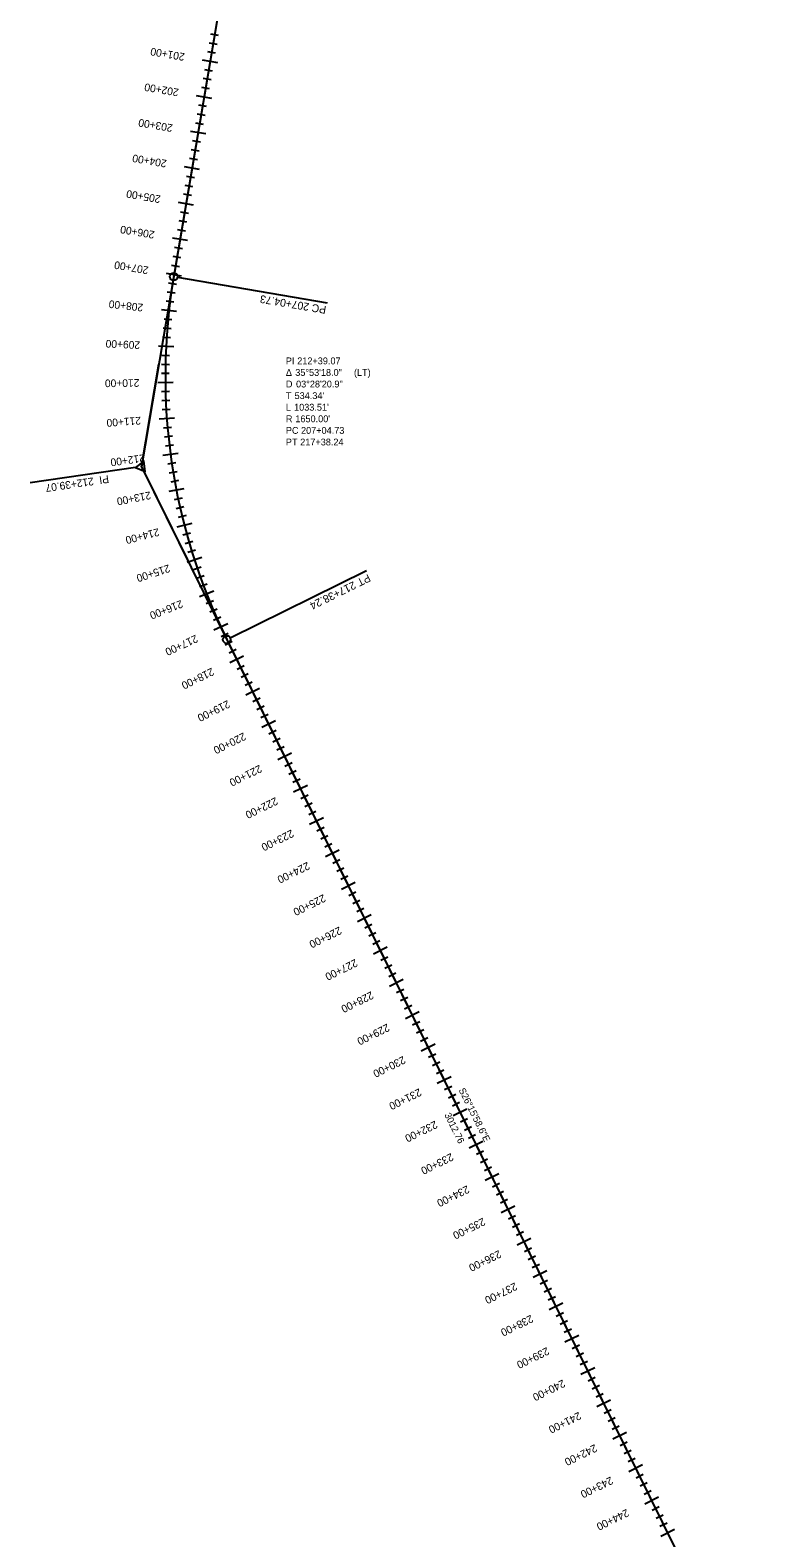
# Model space of a CAD drawing. Extents: x 2823077 to 2858057, y 1248786 to 1289821.
# Drawn here: x 2838680 to 2840753, y 1274641 to 1278821 of the extents above; entities that cross this region are included whole.
import ezdxf

# ---------------------------------------------------------------- set-up
doc = ezdxf.new("R2010")
doc.units = 0
for name, color, linetype in [('_CIVIL_CONSTRUCTION', 7, 'Continuous'), ('Default', 7, 'Continuous'), ('TL_Earth Shoulder Sub', 7, 'Continuous'), ('TL_End Condition Hinge', 7, 'Continuous'), ('TL_Pavement Centerline Sub', 7, 'Continuous'), ('TL_Pavement Edge', 7, 'Continuous'), ('TL_Pavement Edge Sub', 7, 'Continuous'), ('TL_Shoulder Edge', 7, 'Continuous'), ('TL_Shoulder Edge Sub', 7, 'Continuous')]:
    doc.layers.add(name, color=color, linetype=linetype)

msp = doc.modelspace()

# ---------------------------------------------------------------- linework, layer by layer
at = {"layer": '_CIVIL_CONSTRUCTION'}
for p, q in [((2839406.5, 1280075.4), (2839077.9, 1278137.4)), ((2839225.1, 1277131.4), (2840558.4, 1274429.8))]:
    msp.add_line(p, q, dxfattribs=at)
msp.add_arc((2840704.7, 1277861.6), 1650, 170.378, 206.2663, dxfattribs=at)
at = {"layer": 'Default'}
for p, q in [((2839540.6, 1280866.7), (2838988.6, 1277610.6)), ((2838988.6, 1277610.6), (2840753.1, 1274035.2))]:
    msp.add_line(p, q, dxfattribs=at)
msp.add_arc((2840704.7, 1277861.6), 1650, 170.378, 206.2663, dxfattribs=at)
at = {"layer": 'TL_Earth Shoulder Sub'}
for p, q in [((2839077.9, 1278137.4), (2839077.9, 1278137.4)), ((2839503.9, 1278065.2), (2839503.9, 1278065.2)), ((2838988.6, 1277610.6), (2838988.6, 1277610.6)), ((2838679.9, 1277565.4), (2838679.9, 1277565.4)), ((2839612.5, 1277322.6), (2839612.5, 1277322.6)), ((2839225.1, 1277131.4), (2839225.1, 1277131.4))]:
    msp.add_line(p, q, dxfattribs=at)
for centre in [(2839077.9, 1278137.4), (2839225.1, 1277131.4)]:
    msp.add_circle(centre, 10.7, dxfattribs=at)
at = {"layer": 'TL_Pavement Centerline Sub'}
for p, q in [((2839200.1, 1278730.1), (2839158.2, 1278737.2)), ((2839183.4, 1278631.5), (2839141.5, 1278638.6)), ((2839166.6, 1278532.9), (2839124.8, 1278540)), ((2839149.9, 1278434.3), (2839108.1, 1278441.4)), ((2839133.2, 1278335.7), (2839091.3, 1278342.8)), ((2839116.5, 1278237.1), (2839074.6, 1278244.2)), ((2839099.8, 1278138.5), (2839057.9, 1278145.6)), ((2839086, 1278040.7), (2839043.7, 1278045.4)), ((2839078.1, 1277942.4), (2839035.7, 1277944.5)), ((2839076.2, 1277843.7), (2839033.7, 1277843.2)), ((2839080.3, 1277745.1), (2839037.9, 1277742)), ((2839090.3, 1277646.9), (2839048.2, 1277641.3)), ((2839106.3, 1277549.5), (2839064.6, 1277541.4)), ((2839128.1, 1277453.3), (2839087, 1277442.6)), ((2839155.7, 1277358.5), (2839115.3, 1277345.4)), ((2839189.1, 1277265.6), (2839149.5, 1277250.1)), ((2839227.9, 1277174.9), (2839189.4, 1277157)), ((2839271.6, 1277085.5), (2839233.5, 1277066.7)), ((2839315.8, 1276995.8), (2839277.7, 1276977)), ((2839360.1, 1276906.1), (2839322, 1276887.4)), ((2839404.3, 1276816.5), (2839366.3, 1276797.7)), ((2839448.6, 1276726.8), (2839410.5, 1276708)), ((2839492.9, 1276637.1), (2839454.8, 1276618.3)), ((2839537.1, 1276547.5), (2839499, 1276528.7)), ((2839581.4, 1276457.8), (2839543.3, 1276439)), ((2839625.6, 1276368.1), (2839587.5, 1276349.3)), ((2839669.9, 1276278.4), (2839631.8, 1276259.6)), ((2839714.1, 1276188.8), (2839676, 1276170)), ((2839758.4, 1276099.1), (2839720.3, 1276080.3)), ((2839802.6, 1276009.4), (2839764.5, 1275990.6)), ((2839846.9, 1275919.7), (2839808.8, 1275900.9)), ((2839891.1, 1275830.1), (2839853.1, 1275811.3)), ((2839935.4, 1275740.4), (2839897.3, 1275721.6)), ((2839979.7, 1275650.7), (2839941.6, 1275631.9)), ((2840023.9, 1275561), (2839985.8, 1275542.2)), ((2840068.2, 1275471.4), (2840030.1, 1275452.6)), ((2840112.4, 1275381.7), (2840074.3, 1275362.9)), ((2840156.7, 1275292), (2840118.6, 1275273.2)), ((2840200.9, 1275202.3), (2840162.8, 1275183.5)), ((2840245.2, 1275112.7), (2840207.1, 1275093.9)), ((2840289.4, 1275023), (2840251.3, 1275004.2)), ((2840333.7, 1274933.3), (2840295.6, 1274914.5)), ((2840377.9, 1274843.6), (2840339.8, 1274824.8)), ((2840422.2, 1274754), (2840384.1, 1274735.2)), ((2840466.5, 1274664.3), (2840428.4, 1274645.5))]:
    msp.add_line(p, q, dxfattribs=at)
at = {"layer": 'TL_Pavement Edge Sub'}
for p, q in [((2839202.4, 1278805.7), (2839180.7, 1278809.4)), ((2839194.1, 1278756.4), (2839172.3, 1278760.1)), ((2839198.3, 1278781.1), (2839176.5, 1278784.8)), ((2839185.7, 1278707.1), (2839164, 1278710.8)), ((2839181.5, 1278682.5), (2839159.8, 1278686.2)), ((2839177.4, 1278657.9), (2839155.6, 1278661.5)), ((2839164.8, 1278583.9), (2839143.1, 1278587.6)), ((2839169, 1278608.6), (2839147.2, 1278612.2)), ((2839160.7, 1278559.3), (2839138.9, 1278563)), ((2839152.3, 1278510), (2839130.5, 1278513.7)), ((2839143.9, 1278460.7), (2839122.2, 1278464.4)), ((2839148.1, 1278485.3), (2839126.3, 1278489)), ((2839131.4, 1278386.7), (2839109.6, 1278390.4)), ((2839135.6, 1278411.4), (2839113.8, 1278415.1)), ((2839127.2, 1278362.1), (2839105.5, 1278365.8)), ((2839114.7, 1278288.1), (2839092.9, 1278291.8)), ((2839118.9, 1278312.8), (2839097.1, 1278316.5)), ((2839110.5, 1278263.5), (2839088.7, 1278267.2)), ((2839102.2, 1278214.2), (2839080.4, 1278217.9)), ((2839093.8, 1278164.9), (2839072, 1278168.6)), ((2839098, 1278189.5), (2839076.2, 1278193.2)), ((2839081.9, 1278091.1), (2839060.1, 1278094.2)), ((2839085.6, 1278115.7), (2839063.8, 1278119.1)), ((2839078.6, 1278066.5), (2839056.7, 1278069.3)), ((2839073.2, 1278017.2), (2839051.2, 1278019.3)), ((2839069.2, 1277967.7), (2839047.2, 1277969.1)), ((2839071, 1277992.4), (2839049, 1277994.2)), ((2839066.7, 1277918.1), (2839044.7, 1277918.8)), ((2839066.1, 1277893.2), (2839044, 1277893.7)), ((2839065.8, 1277868.4), (2839043.7, 1277868.5)), ((2839066.3, 1277818.7), (2839044.3, 1277818.2)), ((2839067.2, 1277793.9), (2839045.1, 1277793)), ((2839068.4, 1277769.1), (2839046.3, 1277767.9)), ((2839071.9, 1277719.6), (2839049.9, 1277717.7)), ((2839074.3, 1277694.9), (2839052.3, 1277692.6)), ((2839077, 1277670.2), (2839055.1, 1277667.6)), ((2839083.5, 1277621), (2839061.7, 1277617.7)), ((2839087.4, 1277596.4), (2839065.6, 1277592.8)), ((2839091.6, 1277571.9), (2839069.8, 1277568)), ((2839101.1, 1277523.2), (2839079.5, 1277518.6)), ((2839106.4, 1277498.9), (2839084.9, 1277494.1)), ((2839112.1, 1277474.8), (2839090.6, 1277469.6)), ((2839124.5, 1277426.7), (2839103.2, 1277420.8)), ((2839131.3, 1277402.8), (2839110.1, 1277396.6)), ((2839138.4, 1277379), (2839117.3, 1277372.5)), ((2839153.8, 1277331.8), (2839132.9, 1277324.6)), ((2839162, 1277308.3), (2839141.2, 1277300.9)), ((2839170.5, 1277285), (2839149.9, 1277277.3)), ((2839188.7, 1277238.8), (2839168.3, 1277230.4)), ((2839198.3, 1277215.9), (2839178, 1277207.2)), ((2839208.3, 1277193.2), (2839188.1, 1277184.2)), ((2839229.2, 1277148.1), (2839209.3, 1277138.5)), ((2839240.2, 1277125.8), (2839220.4, 1277116)), ((2839251.3, 1277103.4), (2839231.5, 1277093.6)), ((2839273.4, 1277058.5), (2839253.6, 1277048.7)), ((2839284.5, 1277036.1), (2839264.7, 1277026.3)), ((2839295.5, 1277013.7), (2839275.7, 1277003.9)), ((2839317.6, 1276968.8), (2839297.8, 1276959.1)), ((2839328.7, 1276946.4), (2839308.9, 1276936.6)), ((2839339.8, 1276924), (2839320, 1276914.2)), ((2839361.9, 1276879.2), (2839342.1, 1276869.4)), ((2839373, 1276856.7), (2839353.2, 1276847)), ((2839384, 1276834.3), (2839364.2, 1276824.6)), ((2839406.2, 1276789.5), (2839386.4, 1276779.7)), ((2839417.2, 1276767.1), (2839397.4, 1276757.3)), ((2839428.3, 1276744.7), (2839408.5, 1276734.9)), ((2839450.4, 1276699.8), (2839430.6, 1276690)), ((2839461.5, 1276677.4), (2839441.7, 1276667.6)), ((2839472.5, 1276655), (2839452.7, 1276645.2)), ((2839494.7, 1276610.1), (2839474.9, 1276600.4)), ((2839505.7, 1276587.7), (2839485.9, 1276577.9)), ((2839516.8, 1276565.3), (2839497, 1276555.5)), ((2839538.9, 1276520.5), (2839519.1, 1276510.7)), ((2839550, 1276498), (2839530.2, 1276488.3)), ((2839561, 1276475.6), (2839541.2, 1276465.9)), ((2839583.2, 1276430.8), (2839563.4, 1276421)), ((2839594.2, 1276408.4), (2839574.4, 1276398.6)), ((2839605.3, 1276386), (2839585.5, 1276376.2)), ((2839627.4, 1276341.1), (2839607.6, 1276331.3)), ((2839638.5, 1276318.7), (2839618.7, 1276308.9)), ((2839649.6, 1276296.3), (2839629.8, 1276286.5)), ((2839671.7, 1276251.4), (2839651.9, 1276241.7)), ((2839682.7, 1276229), (2839662.9, 1276219.3)), ((2839693.8, 1276206.6), (2839674, 1276196.8)), ((2839715.9, 1276161.8), (2839696.1, 1276152)), ((2839727, 1276139.3), (2839707.2, 1276129.6)), ((2839738.1, 1276116.9), (2839718.3, 1276107.2)), ((2839760.2, 1276072.1), (2839740.4, 1276062.3)), ((2839771.3, 1276049.7), (2839751.5, 1276039.9)), ((2839782.3, 1276027.3), (2839762.5, 1276017.5)), ((2839804.4, 1275982.4), (2839784.6, 1275972.6)), ((2839815.5, 1275960), (2839795.7, 1275950.2)), ((2839826.6, 1275937.6), (2839806.8, 1275927.8)), ((2839848.7, 1275892.7), (2839828.9, 1275883)), ((2839859.8, 1275870.3), (2839840, 1275860.6)), ((2839870.8, 1275847.9), (2839851, 1275838.1)), ((2839893, 1275803.1), (2839873.2, 1275793.3)), ((2839904, 1275780.6), (2839884.2, 1275770.9)), ((2839915.1, 1275758.2), (2839895.3, 1275748.5)), ((2839937.2, 1275713.4), (2839917.4, 1275703.6)), ((2839948.3, 1275691), (2839928.5, 1275681.2)), ((2839959.3, 1275668.6), (2839939.5, 1275658.8)), ((2839981.5, 1275623.7), (2839961.7, 1275613.9)), ((2839992.5, 1275601.3), (2839972.7, 1275591.5)), ((2840003.6, 1275578.9), (2839983.8, 1275569.1)), ((2840025.7, 1275534), (2840005.9, 1275524.3)), ((2840036.8, 1275511.6), (2840017, 1275501.9)), ((2840047.8, 1275489.2), (2840028, 1275479.4)), ((2840070, 1275444.4), (2840050.2, 1275434.6)), ((2840081, 1275422), (2840061.2, 1275412.2)), ((2840092.1, 1275399.5), (2840072.3, 1275389.8)), ((2840114.2, 1275354.7), (2840094.4, 1275344.9)), ((2840125.3, 1275332.3), (2840105.5, 1275322.5)), ((2840136.4, 1275309.9), (2840116.6, 1275300.1)), ((2840158.5, 1275265), (2840138.7, 1275255.2)), ((2840169.5, 1275242.6), (2840149.7, 1275232.8)), ((2840180.6, 1275220.2), (2840160.8, 1275210.4)), ((2840202.7, 1275175.3), (2840182.9, 1275165.6)), ((2840213.8, 1275152.9), (2840194, 1275143.2)), ((2840224.9, 1275130.5), (2840205.1, 1275120.7)), ((2840247, 1275085.7), (2840227.2, 1275075.9)), ((2840258.1, 1275063.3), (2840238.3, 1275053.5)), ((2840269.1, 1275040.8), (2840249.3, 1275031.1)), ((2840291.2, 1274996), (2840271.4, 1274986.2)), ((2840302.3, 1274973.6), (2840282.5, 1274963.8)), ((2840313.4, 1274951.2), (2840293.6, 1274941.4)), ((2840335.5, 1274906.3), (2840315.7, 1274896.5)), ((2840346.6, 1274883.9), (2840326.8, 1274874.1)), ((2840357.6, 1274861.5), (2840337.8, 1274851.7)), ((2840379.8, 1274816.6), (2840360, 1274806.9)), ((2840390.8, 1274794.2), (2840371, 1274784.5)), ((2840401.9, 1274771.8), (2840382.1, 1274762)), ((2840424, 1274727), (2840404.2, 1274717.2)), ((2840435.1, 1274704.6), (2840415.3, 1274694.8)), ((2840446.1, 1274682.1), (2840426.3, 1274672.4))]:
    msp.add_line(p, q, dxfattribs=at)
at = {"layer": 'TL_Shoulder Edge'}
for p, q in [((2839088.5, 1278135.6), (2839503.9, 1278065.2)), ((2838988.6, 1277610.6), (2839036.8, 1277894.5)), ((2838972, 1277608.2), (2838679.9, 1277565.4)), ((2838988.6, 1277610.6), (2839116.1, 1277352.3)), ((2839234.7, 1277136.2), (2839612.5, 1277322.6))]:
    msp.add_line(p, q, dxfattribs=at)
msp.add_lwpolyline([(2838972.2, 1277608.2), (2838998.9, 1277597.6), (2838994.8, 1277626.1)], close=True, dxfattribs=at)

# ---------------------------------------------------------------- texts
at = {"layer": 'TL_Earth Shoulder Sub'}
for s, height, rotation, p in [('207+04.73', 21.6, 170.378, (2839454.9, 1278063.4)), ('PC', 21.6, 170.378, (2839502.2, 1278055.3)), ('212+39.07', 21.26, 188.3221, (2838854.8, 1277580.9)), ('PI ', 21.26, 188.3221, (2838896.7, 1277587)), ('217+38.24', 21.6, 206.2663, (2839576.2, 1277293.5)), ('PT', 21.6, 206.2663, (2839616.9, 1277313.6))]:
    msp.add_text(s, height=height, rotation=rotation, dxfattribs=at).set_placement(p)
at = {"layer": 'TL_End Condition Hinge'}
for s, rotation, p in [('201+00', 170.378, (2839109.8, 1278756.2)), ('202+00', 170.378, (2839093.1, 1278657.6)), ('203+00', 170.378, (2839076.4, 1278559)), ('204+00', 170.378, (2839059.7, 1278460.4)), ('205+00', 170.378, (2839042.9, 1278361.8)), ('206+00', 170.378, (2839026.2, 1278263.2)), ('207+00', 170.378, (2839009.5, 1278164.6)), ('208+00', 173.6863, (2838994.3, 1278061.6)), ('209+00', 177.1588, (2838985.4, 1277957.6)), ('210+00', 180.6313, (2838982.7, 1277853.3)), ('211+00', 184.1037, (2838986.4, 1277749)), ('212+00', 187.5762, (2838996.4, 1277645.1)), ('213+00', 191.0487, (2839012.6, 1277542.1)), ('214+00', 194.5212, (2839035.1, 1277440.2)), ('215+00', 197.9936, (2839063.7, 1277339.8)), ('216+00', 201.4661, (2839098.3, 1277241.4)), ('217+00', 204.9386, (2839138.8, 1277145.2)), ('218+00', 206.2663, (2839183.2, 1277053.7)), ('219+00', 206.2663, (2839227.4, 1276964)), ('220+00', 206.2663, (2839271.7, 1276874.4)), ('221+00', 206.2663, (2839315.9, 1276784.7)), ('222+00', 206.2663, (2839360.2, 1276695)), ('223+00', 206.2663, (2839404.4, 1276605.3)), ('224+00', 206.2663, (2839448.7, 1276515.7)), ('225+00', 206.2663, (2839492.9, 1276426)), ('226+00', 206.2663, (2839537.2, 1276336.3)), ('227+00', 206.2663, (2839581.4, 1276246.6)), ('228+00', 206.2663, (2839625.7, 1276157)), ('229+00', 206.2663, (2839670, 1276067.3)), ('230+00', 206.2663, (2839714.2, 1275977.6)), ('231+00', 206.2663, (2839758.5, 1275887.9)), ('232+00', 206.2663, (2839802.7, 1275798.3)), ('233+00', 206.2663, (2839847, 1275708.6)), ('234+00', 206.2663, (2839891.2, 1275618.9)), ('235+00', 206.2663, (2839935.5, 1275529.2)), ('236+00', 206.2663, (2839979.7, 1275439.6)), ('237+00', 206.2663, (2840024, 1275349.9)), ('238+00', 206.2663, (2840068.2, 1275260.2)), ('239+00', 206.2663, (2840112.5, 1275170.5)), ('240+00', 206.2663, (2840156.8, 1275080.9)), ('241+00', 206.2663, (2840201, 1274991.2)), ('242+00', 206.2663, (2840245.3, 1274901.5)), ('243+00', 206.2663, (2840289.5, 1274811.8)), ('244+00', 206.2663, (2840333.8, 1274722.2))]:
    msp.add_text(s, height=21.26, rotation=rotation, dxfattribs=at).set_placement(p)
at = {"layer": 'TL_Pavement Edge'}
for s, height, p in [('S26°15\'58.6"E', 18.898, (2839867.5, 1275882.9)), ('3012.76', 18.9, (2839827.9, 1275814.1))]:
    msp.add_text(s, height=height, rotation=296.2663, dxfattribs=at).set_placement(p)
at = {"layer": 'TL_Shoulder Edge Sub'}
for s, height, p in [('Δ ', 18.9, (2839389, 1277862.3)), ('PI ', 18.9, (2839389, 1277894.4)), ('35°53\'18.0"', 18.898, (2839415, 1277862.3)), ('212+39.07', 18.9, (2839420.5, 1277894.4)), (' (LT)', 18.9, (2839570.7, 1277862.3)), ('D ', 18.9, (2839389, 1277830.2)), ('03°28\'20.9"', 18.898, (2839417.2, 1277830.2)), ('T ', 18.9, (2839389, 1277798)), ("534.34'", 18.9, (2839413.1, 1277798)), ('L ', 18.9, (2839389, 1277765.9)), ('R ', 18.9, (2839389, 1277733.8)), ("1033.51'", 18.9, (2839411.7, 1277765.9)), ("1650.00'", 18.9, (2839415.2, 1277733.8)), ('PC ', 18.9, (2839389, 1277701.7)), ('207+04.73', 18.9, (2839431, 1277701.7)), ('PT ', 18.9, (2839389, 1277669.5)), ('217+38.24', 18.9, (2839428.7, 1277669.5))]:
    msp.add_text(s, height=height, dxfattribs=at).set_placement(p)

doc.saveas('drawing.dxf')
